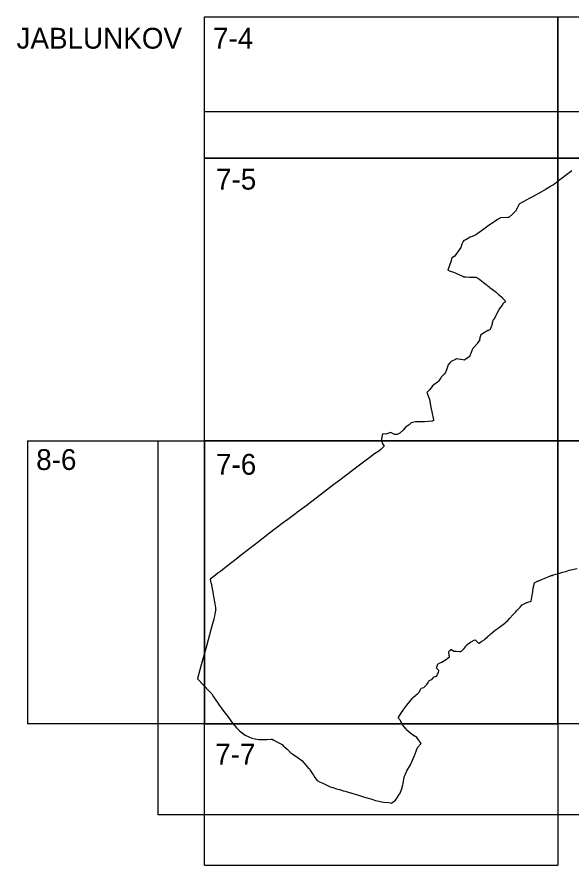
# Model space of a CAD drawing. Extents: x -449577 to -425530, y -1150048 to -1121091.
# Drawn here: x -433468.8 to -433224, y -1126653.4 to -1126278.4 of the extents above; entities that cross this region are included whole.
import ezdxf

# ---------------------------------------------------------------- set-up
doc = ezdxf.new("R2010")
doc.units = 0
for name, color, linetype in [('Vrstva 1', 7, 'Continuous'), ('Vrstva 10', 7, 'Continuous'), ('Vrstva 4', 7, 'Continuous')]:
    doc.layers.add(name, color=color, linetype=linetype)

msp = doc.modelspace()

# ---------------------------------------------------------------- linework, layer by layer
at = {"layer": 'Vrstva 1'}
for points in [[(-433223.64, -1126346.44), (-433224.85, -1126347.4), (-433224.85, -1126347.4), (-433226, -1126348.27), (-433226.57, -1126348.7), (-433227.15, -1126349.14), (-433227.31, -1126349.26), (-433229.44, -1126350.9), (-433230.51, -1126351.72), (-433230.98, -1126352.06), (-433231.74, -1126352.57), (-433231.99, -1126352.73), (-433232.58, -1126353.12), (-433232.62, -1126353.15), (-433232.83, -1126353.29), (-433233.74, -1126353.89), (-433233.75, -1126353.89), (-433234.22, -1126354.15), (-433234.37, -1126354.23), (-433234.55, -1126354.33), (-433235.01, -1126354.58), (-433235.19, -1126354.69), (-433235.35, -1126354.78), (-433235.45, -1126354.84), (-433235.69, -1126354.98), (-433237.35, -1126355.92), (-433237.52, -1126356.01), (-433237.75, -1126356.14), (-433240.22, -1126357.54), (-433240.34, -1126357.61), (-433242.45, -1126358.74), (-433243.47, -1126359.29), (-433246.81, -1126361.1), (-433246.98, -1126361.4), (-433247.04, -1126361.51), (-433247.82, -1126362.97), (-433248.5, -1126364.29), (-433248.64, -1126364.42), (-433248.73, -1126364.5), (-433249.87, -1126365.54), (-433251.38, -1126366.92), (-433251.55, -1126367.07), (-433251.55, -1126367.08), (-433252.02, -1126367.09), (-433255.21, -1126367.18), (-433255.22, -1126367.18), (-433255.65, -1126367.47), (-433256.48, -1126368.04), (-433258.95, -1126369.7), (-433258.99, -1126369.72), (-433259.23, -1126369.9), (-433259.5, -1126370.1), (-433262.48, -1126372.23), (-433262.55, -1126372.28), (-433265.55, -1126374.46), (-433266.02, -1126374.8), (-433266.18, -1126374.86), (-433268.12, -1126375.58), (-433268.13, -1126375.58), (-433268.52, -1126375.82), (-433270.4, -1126376.98), (-433271.32, -1126377.19), (-433271.57, -1126377.7), (-433272.33, -1126379.21), (-433272.34, -1126379.22), (-433272.41, -1126379.48), (-433272.61, -1126380.32), (-433273.44, -1126381.43), (-433274.81, -1126383.38), (-433275.37, -1126384.19), (-433275.4, -1126384.21), (-433276.56, -1126384.85), (-433276.66, -1126384.91), (-433276.73, -1126385.3), (-433276.88, -1126386.11), (-433276.93, -1126386.3), (-433278.22, -1126389.88), (-433278.39, -1126390.36), (-433278.36, -1126390.35), (-433278.34, -1126390.34), (-433277.66, -1126390.6), (-433275.85, -1126391.26), (-433275.23, -1126391.55), (-433272.94, -1126392.63), (-433272.92, -1126392.63), (-433271.76, -1126393.1), (-433271.29, -1126393.28), (-433271.26, -1126393.29), (-433270.83, -1126393.32), (-433270.69, -1126393.33), (-433270.47, -1126393.35), (-433268.87, -1126393.45), (-433267.83, -1126393.52), (-433266.78, -1126393.49), (-433265.94, -1126393.46), (-433265.93, -1126393.46), (-433265.65, -1126393.61), (-433265.28, -1126393.87), (-433264.73, -1126394.25), (-433264.34, -1126394.53), (-433262.78, -1126395.67), (-433262.61, -1126395.79), (-433261.5, -1126396.71), (-433261.11, -1126397.03), (-433260.93, -1126397.18), (-433260.18, -1126397.79), (-433259.91, -1126398.02), (-433259.31, -1126398.51), (-433259.09, -1126398.69), (-433258.45, -1126399.11), (-433257.7, -1126399.61), (-433257.67, -1126399.63), (-433256.91, -1126400.31), (-433256.03, -1126401.09), (-433255.59, -1126401.47), (-433254.58, -1126402.36), (-433254.32, -1126402.59), (-433254.27, -1126402.64), (-433254.17, -1126402.74), (-433254.16, -1126402.75), (-433254.07, -1126402.85), (-433254.04, -1126402.88), (-433252.99, -1126404.11), (-433253, -1126404.12), (-433253.44, -1126404.61), (-433253.5, -1126404.68), (-433254.07, -1126405.31), (-433254.89, -1126406.37), (-433255.06, -1126406.58), (-433255.62, -1126407.3), (-433255.92, -1126407.83), (-433255.94, -1126407.87), (-433255.95, -1126407.89), (-433256.08, -1126408.17), (-433256.88, -1126409.84), (-433257.19, -1126410.48), (-433257.81, -1126411.77), (-433257.92, -1126412.01), (-433257.93, -1126412.01), (-433257.97, -1126412.04), (-433258.26, -1126412.24), (-433258.34, -1126412.28), (-433258.39, -1126412.38), (-433258.48, -1126412.58), (-433258.57, -1126412.86), (-433258.74, -1126413.42), (-433258.75, -1126413.44), (-433258.87, -1126413.94), (-433258.89, -1126414.01), (-433258.88, -1126414.07), (-433258.87, -1126414.15), (-433258.87, -1126414.22), (-433258.88, -1126414.27), (-433259.76, -1126416.6), (-433259.78, -1126416.65), (-433259.8, -1126416.69), (-433259.81, -1126416.7), (-433260.51, -1126417), (-433260.76, -1126417.11), (-433261.23, -1126417.35), (-433263.84, -1126419.04), (-433263.84, -1126419.04), (-433264.21, -1126420.35), (-433264.29, -1126420.61), (-433264.4, -1126421.03), (-433264.46, -1126421.24), (-433264.46, -1126421.25), (-433264.45, -1126421.25), (-433264.28, -1126421.41), (-433264.29, -1126421.42), (-433264.65, -1126421.81), (-433265.45, -1126422.81), (-433265.46, -1126422.82), (-433265.67, -1126423.07), (-433265.67, -1126423.08), (-433265.79, -1126423.23), (-433266.95, -1126424.58), (-433267.49, -1126425.21), (-433268.25, -1126427.16), (-433268.63, -1126428.18), (-433268.76, -1126428.53), (-433270.29, -1126429.63), (-433270.91, -1126430.07), (-433271.09, -1126430.11), (-433271.11, -1126430.11), (-433271.74, -1126430.02), (-433274.58, -1126429.6), (-433275.07, -1126429.84), (-433276.4, -1126430.48), (-433276.94, -1126430.74), (-433276.97, -1126430.77), (-433277.4, -1126431.18), (-433277.57, -1126431.4), (-433278.23, -1126432.25), (-433278.23, -1126432.26), (-433278.9, -1126434.06), (-433279.47, -1126435.56), (-433279.47, -1126435.56), (-433279.61, -1126435.78), (-433279.94, -1126436.15), (-433280.66, -1126436.95), (-433281.36, -1126437.72), (-433281.37, -1126437.74), (-433281.5, -1126437.93), (-433282.57, -1126439.5), (-433283.04, -1126439.88), (-433284.61, -1126441.14), (-433285.28, -1126441.68), (-433285.38, -1126441.76), (-433285.41, -1126441.8), (-433286.53, -1126443.23), (-433287.67, -1126444.54), (-433287.52, -1126444.71), (-433287.51, -1126444.74), (-433287.51, -1126444.75), (-433286.5, -1126447.51), (-433286.22, -1126449.17), (-433285.9, -1126451.12), (-433285.49, -1126453.08), (-433284.76, -1126456.58), (-433284.72, -1126456.78), (-433285.37, -1126457.12), (-433285.49, -1126457.19), (-433288.66, -1126457.45), (-433288.82, -1126457.45), (-433290.31, -1126457.42), (-433292.7, -1126457.4), (-433293.98, -1126457.67), (-433294.58, -1126457.94), (-433295.56, -1126458.74), (-433296.86, -1126459.61), (-433296.95, -1126459.72), (-433298.11, -1126461.14), (-433299.56, -1126462.48), (-433300.25, -1126462.8), (-433300.85, -1126463.08), (-433302.02, -1126463.01), (-433303.63, -1126462.16), (-433305.87, -1126462.83), (-433307.35, -1126462.8), (-433307.73, -1126464.91), (-433307.74, -1126464.93), (-433307.75, -1126465.02), (-433307.46, -1126466.83), (-433306.49, -1126468.15), (-433306.48, -1126468.17), (-433307.22, -1126468.92), (-433307.83, -1126469.48), (-433308.08, -1126469.71), (-433308.88, -1126470.34), (-433310.81, -1126471.57), (-433310.87, -1126471.61), (-433312.84, -1126473.14), (-433312.9, -1126473.18), (-433313.39, -1126473.56), (-433318.05, -1126477.02), (-433318.08, -1126477.05), (-433323.03, -1126480.81), (-433327.29, -1126484.06), (-433328.17, -1126484.72), (-433330.74, -1126486.66), (-433334.74, -1126489.79), (-433337.18, -1126491.66), (-433340.49, -1126494.19), (-433340.54, -1126494.23), (-433345.33, -1126497.74), (-433345.56, -1126497.92), (-433349.17, -1126500.6), (-433351.56, -1126502.42), (-433353.53, -1126503.9), (-433355.85, -1126505.65), (-433356.08, -1126505.82), (-433357.21, -1126506.71), (-433362.03, -1126510.51), (-433365.92, -1126513.46), (-433370.14, -1126516.71), (-433371.43, -1126517.71), (-433373.82, -1126519.59), (-433375, -1126520.51), (-433378.94, -1126523.56), (-433379.87, -1126524.27), (-433381.11, -1126525.23), (-433383.43, -1126527.03), (-433383.43, -1126527.03), (-433383.39, -1126527.21), (-433383.1, -1126528.59), (-433383.07, -1126528.75), (-433382.54, -1126531.29), (-433382.38, -1126532.02), (-433382.38, -1126532.06), (-433381.45, -1126537.94), (-433381.44, -1126537.97), (-433381.14, -1126539.7), (-433381.14, -1126539.72), (-433381.08, -1126540.09), (-433381.02, -1126540.51), (-433381.05, -1126540.88), (-433381.2, -1126541.61), (-433381.58, -1126543.4), (-433381.87, -1126544.58), (-433381.89, -1126544.63), (-433383, -1126548.8), (-433385.1, -1126556.68), (-433387.09, -1126563.9), (-433389.02, -1126571), (-433389.03, -1126571.04), (-433383.75, -1126576.64), (-433382.7, -1126577.77), (-433381.94, -1126578.99), (-433379.92, -1126582.05), (-433379.87, -1126582.12), (-433378.86, -1126583.53), (-433378.7, -1126583.74), (-433376.82, -1126586.22), (-433376.25, -1126586.96), (-433376.22, -1126587), (-433375.7, -1126587.72), (-433374.32, -1126589.62), (-433373.99, -1126590.07), (-433371.84, -1126592.79), (-433370.44, -1126594.01), (-433368.04, -1126595.99), (-433366.3, -1126596.74), (-433365.11, -1126597.26), (-433364.98, -1126597.31), (-433363.65, -1126597.59), (-433363.51, -1126597.62), (-433361.89, -1126597.95), (-433361.86, -1126597.95), (-433360.9, -1126597.93), (-433360.52, -1126597.93), (-433360, -1126597.92), (-433359.32, -1126597.91), (-433358.41, -1126597.87), (-433356.46, -1126597.71), (-433356.01, -1126597.78), (-433355.35, -1126598.13), (-433353.63, -1126599.08), (-433351.67, -1126600.18), (-433351.15, -1126600.66), (-433350.43, -1126601.34), (-433349.63, -1126602.09), (-433348.31, -1126603.39), (-433348.17, -1126603.49), (-433346.98, -1126604.34), (-433344.57, -1126606.05), (-433342.93, -1126607.23), (-433341.88, -1126608.41), (-433340.24, -1126610.23), (-433339.6, -1126610.94), (-433339.24, -1126611.53), (-433338.78, -1126612.27), (-433337.84, -1126613.74), (-433337.21, -1126614.66), (-433336.17, -1126616.1), (-433335.1, -1126616.61), (-433333.72, -1126617.26), (-433332.41, -1126617.87), (-433330.44, -1126618.76), (-433329.31, -1126619.11), (-433327.59, -1126619.68), (-433327.44, -1126619.73), (-433326.35, -1126620.05), (-433324.93, -1126620.47), (-433324.92, -1126620.47), (-433324.71, -1126620.53), (-433324.65, -1126620.55), (-433323.79, -1126620.81), (-433321.4, -1126621.5), (-433321.28, -1126621.54), (-433320.8, -1126621.68), (-433317.87, -1126622.55), (-433315.18, -1126623.38), (-433314.84, -1126623.48), (-433314.08, -1126623.71), (-433312.07, -1126624.33), (-433310.34, -1126624.88), (-433306.88, -1126625.62)], [(-433306.88, -1126625.62), (-433304.49, -1126625.81), (-433303.29, -1126626.04), (-433303.18, -1126625.95), (-433301.6, -1126624.68), (-433300.57, -1126623.2), (-433300.46, -1126623.05), (-433299.94, -1126622.29), (-433299.83, -1126622.12), (-433299.69, -1126621.89), (-433299.31, -1126621.26), (-433299.04, -1126620.43), (-433299.02, -1126620.36), (-433299, -1126620.31), (-433298.97, -1126620.2), (-433298.94, -1126620.11), (-433298.94, -1126620.1), (-433298.31, -1126617.9), (-433298.17, -1126617.38), (-433297.72, -1126614.63), (-433297.72, -1126614.63), (-433297.53, -1126614.19), (-433297.27, -1126613.57), (-433296.48, -1126611.74), (-433294.91, -1126609.09), (-433293.16, -1126604.96), (-433292.84, -1126604.32), (-433292.8, -1126604.19), (-433292.41, -1126603.09), (-433291.82, -1126601.42), (-433290.14, -1126599.71), (-433291.07, -1126598.47), (-433291.13, -1126598.38), (-433291.18, -1126598.32), (-433291.21, -1126598.28), (-433291.28, -1126598.18), (-433291.33, -1126598.1), (-433291.41, -1126597.98), (-433291.77, -1126597.46), (-433292.14, -1126597), (-433292.71, -1126596.63), (-433292.81, -1126596.57), (-433294.46, -1126595.5), (-433296.65, -1126593.56), (-433296.78, -1126593.39), (-433296.81, -1126593.35), (-433296.89, -1126593.25), (-433297.23, -1126592.83), (-433297.56, -1126592.42), (-433297.82, -1126592.1), (-433298.3, -1126591.51), (-433298.38, -1126591.41), (-433298.88, -1126590.45), (-433299.17, -1126589.89), (-433299.4, -1126589.46), (-433299.45, -1126589.37), (-433299.49, -1126589.32), (-433299.75, -1126589.03), (-433299.95, -1126588.8), (-433300.21, -1126588.51), (-433300.43, -1126588.26), (-433298.57, -1126585.52), (-433298.48, -1126585.4), (-433298.16, -1126584.95), (-433297.84, -1126584.51), (-433296.51, -1126582.68), (-433293.83, -1126579.42), (-433293.48, -1126579.1), (-433292.77, -1126578.4), (-433292.66, -1126578.31), (-433292.47, -1126578.17), (-433291.87, -1126577.69), (-433291.01, -1126576.85), (-433290.6, -1126576.09), (-433290.13, -1126575.22), (-433289.08, -1126574.98), (-433287.68, -1126573.55), (-433287.14, -1126572.7), (-433287.13, -1126572.69), (-433287.13, -1126572.67), (-433286.92, -1126572.34), (-433286.87, -1126572.26), (-433286.63, -1126571.87), (-433285.47, -1126571.43), (-433284.45, -1126570.25), (-433283.92, -1126570.05), (-433283.8, -1126570), (-433283.38, -1126569.84), (-433283.16, -1126569.45), (-433283.11, -1126569.36), (-433282.94, -1126569.06), (-433282.53, -1126568.32), (-433282.33, -1126567.41), (-433282.33, -1126567.39), (-433282.32, -1126567.38), (-433283.37, -1126566.39), (-433283.39, -1126566.38), (-433283.4, -1126566.36), (-433283.45, -1126566.32), (-433282.8, -1126564.52), (-433282.73, -1126564.32), (-433282.57, -1126564.26), (-433281.84, -1126563.97), (-433281.15, -1126563.7), (-433281.03, -1126563.65), (-433279.82, -1126562.94), (-433279.7, -1126562.86), (-433279.7, -1126562.86), (-433279.69, -1126562.85), (-433279.57, -1126562.78), (-433277.71, -1126561.38), (-433277.71, -1126561.34), (-433277.74, -1126561.18), (-433277.81, -1126560.7), (-433277.87, -1126560.35), (-433277.97, -1126559.73), (-433277.99, -1126559.62), (-433278.01, -1126559.49), (-433278.03, -1126559.32), (-433278.06, -1126559.18), (-433277.52, -1126558.62), (-433276.96, -1126558.05), (-433276.92, -1126558), (-433276.78, -1126558.1), (-433275.78, -1126558.89), (-433275.1, -1126558.9), (-433275.04, -1126558.9), (-433274.79, -1126558.91), (-433274.63, -1126558.91), (-433273.32, -1126558.93), (-433272.69, -1126558.95), (-433272.42, -1126558.79), (-433272.39, -1126558.77), (-433272.27, -1126558.7), (-433272.13, -1126558.61), (-433272.09, -1126558.58), (-433271.55, -1126557.98), (-433271.44, -1126557.86), (-433271.35, -1126557.76), (-433271.18, -1126557.58), (-433271.1, -1126557.49), (-433270.99, -1126557.37), (-433270.96, -1126557.33), (-433270.93, -1126557.3), (-433270.88, -1126557.24), (-433270.79, -1126557.13), (-433270.39, -1126556.63), (-433270.18, -1126556.37), (-433269.93, -1126556.05), (-433269.82, -1126555.97), (-433268.36, -1126554.9), (-433268.15, -1126554.77), (-433266.79, -1126554), (-433266.39, -1126553.77), (-433266.39, -1126553.77), (-433266.25, -1126553.92), (-433265.54, -1126554.63), (-433265.17, -1126555.01), (-433264.99, -1126555.18), (-433264.84, -1126555.33), (-433264.75, -1126555.29), (-433263.47, -1126554.52), (-433263.38, -1126554.47), (-433262.45, -1126553.91), (-433262.41, -1126553.88), (-433262.08, -1126553.59), (-433262.03, -1126553.55), (-433261.86, -1126553.4), (-433261.85, -1126553.39), (-433261.85, -1126553.39), (-433261.81, -1126553.35), (-433261.77, -1126553.31), (-433260.88, -1126552.5), (-433260.86, -1126552.49), (-433260.27, -1126551.95), (-433260.16, -1126551.86), (-433260.05, -1126551.76), (-433260.05, -1126551.76), (-433260.04, -1126551.76), (-433260.04, -1126551.76), (-433260.04, -1126551.75), (-433260.03, -1126551.75), (-433260.02, -1126551.74), (-433260.02, -1126551.74), (-433260.01, -1126551.73), (-433260.01, -1126551.73), (-433260, -1126551.73), (-433260, -1126551.73), (-433259.42, -1126551.24), (-433257.43, -1126549.56), (-433256.23, -1126548.71), (-433256.11, -1126548.63), (-433256.06, -1126548.59), (-433256.04, -1126548.58), (-433255.99, -1126548.55), (-433255.63, -1126548.28), (-433254.39, -1126547.34), (-433254.21, -1126547.2), (-433254, -1126547.04), (-433253.98, -1126547.02), (-433253.1, -1126546.35), (-433252.75, -1126546.08), (-433252.7, -1126546.02), (-433252.61, -1126545.92), (-433251.97, -1126545.24), (-433251.07, -1126544.26), (-433249.71, -1126542.85), (-433249.49, -1126542.62), (-433249.24, -1126542.34), (-433248.4, -1126541.39), (-433248.11, -1126541.07), (-433247.91, -1126540.86), (-433247.62, -1126540.54), (-433246.44, -1126539.35), (-433245.51, -1126538.33), (-433243.45, -1126537.32), (-433243.29, -1126537.27), (-433243.09, -1126537.19), (-433241.65, -1126536.7), (-433241.5, -1126535.83), (-433241.34, -1126534.96), (-433240.92, -1126532.59), (-433240.84, -1126532.12), (-433240.51, -1126530.24), (-433240.31, -1126529.36), (-433240.28, -1126529.24), (-433240.23, -1126529.05), (-433240.22, -1126529.01), (-433240.2, -1126528.94), (-433240.19, -1126528.9), (-433240.18, -1126528.85), (-433240.17, -1126528.81), (-433240.16, -1126528.79), (-433240.1, -1126528.58), (-433239.02, -1126528.04), (-433238.73, -1126527.9), (-433238.71, -1126527.89), (-433238.46, -1126527.76), (-433238.41, -1126527.74), (-433236.64, -1126527.02), (-433236.61, -1126527.01), (-433236.58, -1126526.99), (-433235.78, -1126526.68), (-433234.82, -1126526.28), (-433234.01, -1126525.94), (-433233.07, -1126525.55), (-433232.99, -1126525.52), (-433232.38, -1126525.28), (-433232.53, -1126525.44), (-433232.29, -1126525.35), (-433231.8, -1126525.15), (-433231.27, -1126524.99), (-433229.57, -1126524.47), (-433228.98, -1126524.3), (-433228.53, -1126524.18), (-433227.64, -1126523.93), (-433226.33, -1126523.55), (-433224.79, -1126523.09), (-433221.25, -1126522.22)]]:
    msp.add_lwpolyline(points, dxfattribs=at)
at = {"layer": 'Vrstva 10'}
msp.add_lwpolyline([(-433073.49, -1126320.23), (-433073.49, -1126631.21), (-433406.36, -1126631.21), (-433406.36, -1126465.91), (-433385.99, -1126465.91), (-433385.99, -1126340.91), (-433385.99, -1126320.23), (-433073.49, -1126320.23)], dxfattribs=at)
at = {"layer": 'Vrstva 4'}
for p, q in [((-433385.99, -1126278.41), (-433073.49, -1126278.41)), ((-433464.12, -1126465.91), (-433464.12, -1126590.91)), ((-433385.99, -1126653.41), (-433229.74, -1126653.41))]:
    msp.add_line(p, q, dxfattribs=at)
for points in [[(-433229.74, -1126278.41), (-433229.74, -1126340.91), (-433385.99, -1126340.91), (-433385.99, -1126278.41)], [(-433073.49, -1126278.41), (-433073.49, -1126340.91), (-433229.74, -1126340.91), (-433229.74, -1126278.41)], [(-433464.12, -1126465.91), (-433385.99, -1126465.91), (-433385.99, -1126590.91), (-433464.12, -1126590.91)], [(-433385.99, -1126653.41), (-433385.99, -1126590.91), (-433229.74, -1126590.91), (-433229.74, -1126653.41)]]:
    msp.add_lwpolyline(points, dxfattribs=at)
for points in [[(-433229.74, -1126340.91), (-433229.74, -1126465.91), (-433385.99, -1126465.91), (-433385.99, -1126340.91)], [(-433073.49, -1126340.91), (-433073.49, -1126465.91), (-433229.74, -1126465.91), (-433229.74, -1126340.91)], [(-433229.74, -1126465.91), (-433229.74, -1126590.91), (-433385.99, -1126590.91), (-433385.99, -1126465.91)], [(-433073.49, -1126465.91), (-433073.49, -1126590.91), (-433229.74, -1126590.91), (-433229.74, -1126465.91)]]:
    msp.add_lwpolyline(points, close=True, dxfattribs=at)

# ---------------------------------------------------------------- texts
at = {"layer": 'Vrstva 1'}
for s, p in [('JABLUNKOV', (-433469.03, -1126292.41)), ('7-4', (-433382.18, -1126292.41)), ('7-5', (-433380.87, -1126354.75)), ('8-6', (-433460.34, -1126478.72)), ('7-6', (-433380.87, -1126480.82)), ('7-7', (-433381.23, -1126608.99))]:
    msp.add_text(s, height=9.2, dxfattribs=at).set_placement(p)

doc.saveas('drawing.dxf')
